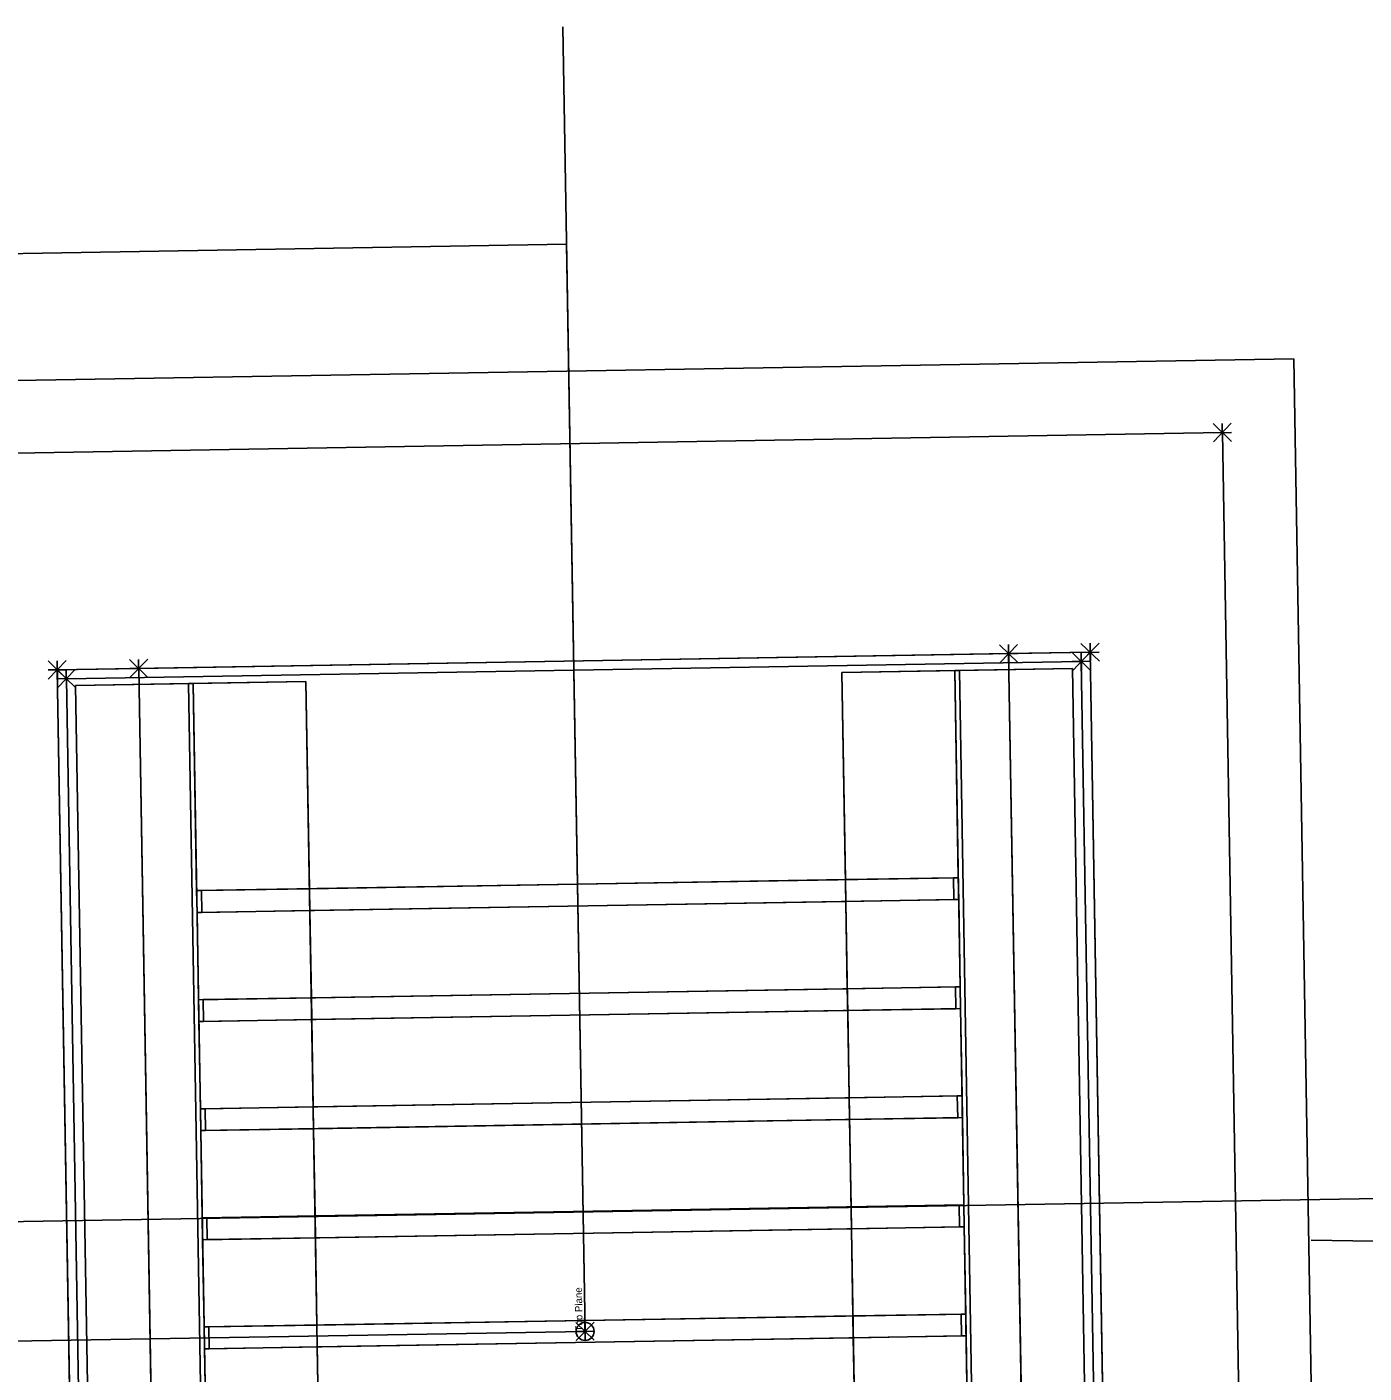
# Model space of a CAD drawing. Extents: x 925371 to 925937, y 853654 to 858024.
# Drawn here: x 925745.198 to 925748.272, y 853953.462 to 853956.558 of the extents above; entities that cross this region are included whole.
import ezdxf

# ---------------------------------------------------------------- set-up
doc = ezdxf.new("R2010")
doc.units = 0
for name, color, linetype in [('NonPlottingEle_dp', 7, 'Continuous'), ('PipeCulvert', 7, 'Continuous'), ('PipeCulvert_ex', 7, 'Continuous')]:
    doc.layers.add(name, color=color, linetype=linetype)

msp = doc.modelspace()

# ---------------------------------------------------------------- linework, layer by layer
at = {"layer": 'NonPlottingEle_dp'}
msp.add_lwpolyline([(925743.7004, 853937.7833), (925743.4284, 853953.781), (925751.9636, 853953.9261)], dxfattribs=at)
at = {"layer": 'PipeCulvert'}
msp.add_line((925748.1503, 853953.7676), (925856.5217, 853952.1731), dxfattribs=at)
at = {"layer": 'PipeCulvert_ex'}
for p, q in [((925746.4812, 853953.5581), (925746.4302, 853956.5577)), ((925744.7772, 853955.7378), (925748.1101, 853955.7945)), ((925748.1101, 853955.7945), (925744.7772, 853955.7378)), ((925748.1101, 853955.7945), (925748.1101, 853955.7945)), ((925748.1101, 853955.7945), (925748.1852, 853951.3784)), ((925748.1852, 853951.3784), (925748.1101, 853955.7945)), ((925747.6423, 853955.1198), (925745.2677, 853955.0794)), ((925745.4551, 853955.0826), (925747.4548, 853955.1166)), ((925747.4548, 853955.1166), (925747.6423, 853955.1198)), ((925747.4548, 853955.1166), (925747.4548, 853955.1166)), ((925747.5073, 853952.0337), (925747.4548, 853955.1166)), ((925747.5073, 853952.0337), (925747.4548, 853955.1166)), ((925747.6423, 853955.1198), (925747.6947, 853952.0369)), ((925747.6947, 853952.0369), (925747.6423, 853955.1198)), ((925747.6423, 853955.1198), (925747.6423, 853955.1198)), ((925745.2677, 853955.0794), (925745.4551, 853955.0826)), ((925745.4551, 853955.0826), (925745.4551, 853955.0826)), ((925745.4551, 853955.0826), (925745.5075, 853951.9997)), ((925745.4551, 853955.0826), (925745.5075, 853951.9997)), ((925747.3311, 853955.078), (925747.6013, 853955.0826)), ((925747.6013, 853955.0826), (925747.3419, 853955.0782)), ((925747.6525, 853952.0726), (925747.6013, 853955.0826)), ((925747.6525, 853952.0726), (925747.6013, 853955.0826)), ((925747.6013, 853955.0826), (925747.6013, 853955.0826)), ((925745.3201, 853951.9965), (925745.2677, 853955.0794)), ((925745.2677, 853955.0794), (925745.3201, 853951.9965)), ((925745.2677, 853955.0794), (925745.2677, 853955.0794)), ((925745.5693, 853955.048), (925745.8395, 853955.0526)), ((925745.8395, 853955.0526), (925745.5801, 853955.0482)), ((925745.8907, 853952.0427), (925745.8395, 853955.0526)), ((925745.8476, 853954.5761), (925745.8395, 853955.0526)), ((925745.8395, 853955.0526), (925745.8395, 853955.0526)), ((925747.3419, 853955.0782), (925747.0717, 853955.0736)), ((925747.0717, 853955.0736), (925747.3311, 853955.078)), ((925747.1229, 853952.0636), (925747.0717, 853955.0736)), ((925747.0798, 853954.597), (925747.0717, 853955.0736)), ((925747.0717, 853955.0736), (925747.0717, 853955.0736)), ((925747.3822, 853952.068), (925747.3311, 853955.078)), ((925747.3392, 853954.6014), (925747.3311, 853955.078)), ((925747.3311, 853955.078), (925747.3311, 853955.078)), ((925747.3931, 853952.0682), (925747.3419, 853955.0782)), ((925747.3931, 853952.0682), (925747.3419, 853955.0782)), ((925747.3419, 853955.0782), (925747.3419, 853955.0782)), ((925745.5801, 853955.0482), (925745.3099, 853955.0436)), ((925745.3099, 853955.0436), (925745.5693, 853955.048)), ((925745.3611, 853952.0337), (925745.3099, 853955.0436)), ((925745.3611, 853952.0337), (925745.3099, 853955.0436)), ((925745.3099, 853955.0436), (925745.3099, 853955.0436)), ((925745.6205, 853952.0381), (925745.5693, 853955.048)), ((925745.6205, 853952.0381), (925745.5693, 853955.048)), ((925745.5693, 853955.048), (925745.5693, 853955.048)), ((925745.6313, 853952.0382), (925745.5801, 853955.0482)), ((925745.5882, 853954.5716), (925745.5801, 853955.0482)), ((925745.5801, 853955.0482), (925745.5801, 853955.0482)), ((925747.3392, 853954.6014), (925745.5882, 853954.5716)), ((925745.8476, 853954.5761), (925747.0798, 853954.597)), ((925747.0798, 853954.597), (925747.3284, 853954.6012)), ((925747.0806, 853954.5468), (925747.0798, 853954.597)), ((925747.3284, 853954.6012), (925747.3392, 853954.6014)), ((925747.3292, 853954.5511), (925747.3284, 853954.6012)), ((925747.34, 853954.5513), (925747.3392, 853954.6014)), ((925747.3392, 853954.6014), (925747.3392, 853954.6014)), ((925745.5882, 853954.5716), (925745.5991, 853954.5718)), ((925745.5891, 853954.5215), (925745.5882, 853954.5716)), ((925745.5882, 853954.5716), (925745.5882, 853954.5716)), ((925745.5991, 853954.5718), (925745.8476, 853954.5761)), ((925745.5999, 853954.5217), (925745.5991, 853954.5718)), ((925745.8485, 853954.5259), (925745.8476, 853954.5761)), ((925747.34, 853954.5513), (925745.5891, 853954.5215)), ((925745.5999, 853954.5217), (925745.8485, 853954.5259)), ((925745.8485, 853954.5259), (925747.0806, 853954.5468)), ((925745.8519, 853954.3252), (925745.8485, 853954.5259)), ((925747.0806, 853954.5468), (925747.3292, 853954.5511)), ((925747.084, 853954.3462), (925747.0806, 853954.5468)), ((925747.3292, 853954.5511), (925747.34, 853954.5513)), ((925747.3434, 853954.3506), (925747.34, 853954.5513)), ((925747.34, 853954.5513), (925747.34, 853954.5513)), ((925745.5891, 853954.5215), (925745.5999, 853954.5217)), ((925745.5925, 853954.3208), (925745.5891, 853954.5215)), ((925745.5891, 853954.5215), (925745.5891, 853954.5215)), ((925747.3434, 853954.3506), (925745.5925, 853954.3208)), ((925745.8519, 853954.3252), (925747.084, 853954.3462)), ((925747.084, 853954.3462), (925747.3326, 853954.3504)), ((925747.0849, 853954.296), (925747.084, 853954.3462)), ((925747.3326, 853954.3504), (925747.3434, 853954.3506)), ((925747.3335, 853954.3002), (925747.3326, 853954.3504)), ((925747.3443, 853954.3004), (925747.3434, 853954.3506)), ((925747.3434, 853954.3506), (925747.3434, 853954.3506)), ((925745.5925, 853954.3208), (925745.6033, 853954.321)), ((925745.5934, 853954.2706), (925745.5925, 853954.3208)), ((925745.5925, 853954.3208), (925745.5925, 853954.3208)), ((925745.6033, 853954.321), (925745.8519, 853954.3252)), ((925745.6042, 853954.2708), (925745.6033, 853954.321)), ((925745.8528, 853954.2751), (925745.8519, 853954.3252)), ((925747.3443, 853954.3004), (925745.5934, 853954.2706)), ((925745.8528, 853954.2751), (925747.0849, 853954.296)), ((925747.0849, 853954.296), (925747.3335, 853954.3002)), ((925747.0883, 853954.0953), (925747.0849, 853954.296)), ((925747.3335, 853954.3002), (925747.3443, 853954.3004)), ((925747.3477, 853954.0998), (925747.3443, 853954.3004)), ((925747.3443, 853954.3004), (925747.3443, 853954.3004)), ((925745.5934, 853954.2706), (925745.6042, 853954.2708)), ((925745.5968, 853954.07), (925745.5934, 853954.2706)), ((925745.5934, 853954.2706), (925745.5934, 853954.2706)), ((925745.6042, 853954.2708), (925745.8528, 853954.2751)), ((925745.8562, 853954.0744), (925745.8528, 853954.2751)), ((925747.3477, 853954.0998), (925745.5968, 853954.07)), ((925745.8562, 853954.0744), (925747.0883, 853954.0953)), ((925747.0883, 853954.0953), (925747.3369, 853954.0996)), ((925747.0892, 853954.0452), (925747.0883, 853954.0953)), ((925747.3369, 853954.0996), (925747.3477, 853954.0998)), ((925747.3377, 853954.0494), (925747.3369, 853954.0996)), ((925747.3486, 853954.0496), (925747.3477, 853954.0998)), ((925747.3477, 853954.0998), (925747.3477, 853954.0998)), ((925745.5968, 853954.07), (925745.6076, 853954.0702)), ((925745.5976, 853954.0198), (925745.5968, 853954.07)), ((925745.5968, 853954.07), (925745.5968, 853954.07)), ((925745.6076, 853954.0702), (925745.8562, 853954.0744)), ((925745.6084, 853954.02), (925745.6076, 853954.0702)), ((925745.857, 853954.0242), (925745.8562, 853954.0744)), ((925747.3486, 853954.0496), (925745.5976, 853954.0198)), ((925745.857, 853954.0242), (925747.0892, 853954.0452)), ((925747.0892, 853954.0452), (925747.3377, 853954.0494)), ((925747.0926, 853953.8445), (925747.0892, 853954.0452)), ((925747.3377, 853954.0494), (925747.3486, 853954.0496)), ((925747.352, 853953.8489), (925747.3486, 853954.0496)), ((925747.3486, 853954.0496), (925747.3486, 853954.0496)), ((925745.5976, 853954.0198), (925745.6084, 853954.02)), ((925745.601, 853953.8192), (925745.5976, 853954.0198)), ((925745.5976, 853954.0198), (925745.5976, 853954.0198)), ((925745.6084, 853954.02), (925745.857, 853954.0242)), ((925745.8604, 853953.8236), (925745.857, 853954.0242)), ((925747.352, 853953.8489), (925745.601, 853953.8192)), ((925745.8604, 853953.8236), (925747.0926, 853953.8445)), ((925747.0926, 853953.8445), (925747.3412, 853953.8487)), ((925747.0934, 853953.7943), (925747.0926, 853953.8445)), ((925747.3412, 853953.8487), (925747.352, 853953.8489)), ((925747.342, 853953.7986), (925747.3412, 853953.8487)), ((925747.3528, 853953.7988), (925747.352, 853953.8489)), ((925747.352, 853953.8489), (925747.352, 853953.8489)), ((925745.601, 853953.8192), (925745.6118, 853953.8193)), ((925745.6019, 853953.769), (925745.601, 853953.8192)), ((925745.601, 853953.8192), (925745.601, 853953.8192)), ((925745.6118, 853953.8193), (925745.8604, 853953.8236)), ((925745.6127, 853953.7692), (925745.6118, 853953.8193)), ((925745.8613, 853953.7734), (925745.8604, 853953.8236)), ((925747.3528, 853953.7988), (925745.6019, 853953.769)), ((925745.8613, 853953.7734), (925747.0934, 853953.7943)), ((925747.0934, 853953.7943), (925747.342, 853953.7986)), ((925747.0968, 853953.5937), (925747.0934, 853953.7943)), ((925747.342, 853953.7986), (925747.3528, 853953.7988)), ((925747.3562, 853953.5981), (925747.3528, 853953.7988)), ((925747.3528, 853953.7988), (925747.3528, 853953.7988)), ((925745.6019, 853953.769), (925745.6127, 853953.7692)), ((925745.6053, 853953.5683), (925745.6019, 853953.769)), ((925745.6019, 853953.769), (925745.6019, 853953.769)), ((925745.6127, 853953.7692), (925745.8613, 853953.7734)), ((925745.8647, 853953.5727), (925745.8613, 853953.7734)), ((925747.3562, 853953.5981), (925745.6053, 853953.5683)), ((925747.0968, 853953.5937), (925747.3454, 853953.5979)), ((925747.3454, 853953.5979), (925747.3562, 853953.5981)), ((925747.3463, 853953.5477), (925747.3454, 853953.5979)), ((925747.3571, 853953.5479), (925747.3562, 853953.5981)), ((925747.3562, 853953.5981), (925747.3562, 853953.5981)), ((925745.6053, 853953.5683), (925745.6161, 853953.5685)), ((925745.6062, 853953.5182), (925745.6053, 853953.5683)), ((925745.6053, 853953.5683), (925745.6053, 853953.5683)), ((925745.6161, 853953.5685), (925745.8647, 853953.5727)), ((925745.617, 853953.5183), (925745.6161, 853953.5685)), ((925745.8647, 853953.5727), (925747.0968, 853953.5937)), ((925745.8656, 853953.5226), (925745.8647, 853953.5727)), ((925747.0977, 853953.5435), (925747.0968, 853953.5937)), ((925747.3571, 853953.5479), (925745.6062, 853953.5182)), ((925745.8656, 853953.5226), (925747.0977, 853953.5435)), ((925746.4812, 853953.5581), (925746.4812, 853953.5581)), ((925746.4812, 853953.5581), (925746.4812, 853953.5581)), ((925747.0977, 853953.5435), (925747.3463, 853953.5477)), ((925747.1011, 853953.3428), (925747.0977, 853953.5435)), ((925747.3463, 853953.5477), (925747.3571, 853953.5479)), ((925747.3605, 853953.3473), (925747.3571, 853953.5479)), ((925747.3571, 853953.5479), (925747.3571, 853953.5479)), ((925745.6062, 853953.5182), (925745.617, 853953.5183)), ((925745.6096, 853953.3175), (925745.6062, 853953.5182)), ((925745.6062, 853953.5182), (925745.6062, 853953.5182)), ((925745.617, 853953.5183), (925745.8656, 853953.5226)), ((925745.869, 853953.3219), (925745.8656, 853953.5226))]:
    msp.add_line(p, q, dxfattribs=at)
for points in [[(925746.4387, 853956.0578), (925743.9391, 853956.0153)], [(925746.4812, 853953.5581), (925746.4387, 853956.0578)], [(925747.9674, 853955.6045), (925747.9251, 853955.6455)], [(925747.9258, 853955.6038), (925747.9667, 853955.6462)], [(925747.9466, 853955.6042), (925747.9459, 853955.6458)], [(925747.9463, 853955.625), (925744.9467, 853955.574)], [(925747.9463, 853955.625), (925744.9467, 853955.574)], [(925747.9463, 853955.625), (925744.9467, 853955.574)], [(925747.9463, 853955.625), (925744.9467, 853955.574)], [(925747.9463, 853955.625), (925744.9467, 853955.574)], [(925747.9671, 853955.6253), (925747.9254, 853955.6246)], [(925747.9463, 853955.625), (925747.9463, 853955.625)], [(925748.0157, 853951.5423), (925747.9463, 853955.625)], [(925748.0157, 853951.5423), (925747.9463, 853955.625)], [(925747.9463, 853955.625), (925747.9463, 853955.625)], [(925747.9463, 853955.625), (925747.9463, 853955.625)], [(925748.0157, 853951.5423), (925747.9463, 853955.625)], [(925747.9463, 853955.625), (925747.9463, 853955.625)], [(925748.0157, 853951.5423), (925747.9463, 853955.625)], [(925748.0157, 853951.5423), (925747.9463, 853955.625)], [(925747.9463, 853955.625), (925747.9463, 853955.625)], [(925747.9463, 853955.625), (925747.9463, 853955.625)], [(925747.6423, 853955.1197), (925745.2677, 853955.0794)], [(925747.6423, 853955.1197), (925745.2677, 853955.0794)], [(925747.6423, 853955.1197), (925745.2677, 853955.0794)], [(925747.4548, 853955.1166), (925745.4551, 853955.0826)], [(925747.4548, 853955.1166), (925745.4551, 853955.0826)], [(925747.4548, 853955.1166), (925745.4551, 853955.0826)], [(925747.4548, 853955.1166), (925745.4551, 853955.0826)], [(925745.4551, 853955.0826), (925747.4548, 853955.1166)], [(925747.476, 853955.0961), (925747.4337, 853955.137)], [(925747.4757, 853955.1169), (925747.434, 853955.1162)], [(925747.4344, 853955.0954), (925747.4753, 853955.1377)], [(925747.4552, 853955.0957), (925747.4545, 853955.1374)], [(925747.4548, 853955.1166), (925747.4548, 853955.1166)], [(925747.5073, 853952.0337), (925747.4548, 853955.1166)], [(925747.5073, 853952.0337), (925747.4548, 853955.1166)], [(925747.4548, 853955.1166), (925747.4548, 853955.1166)], [(925747.4548, 853955.1166), (925747.4548, 853955.1166)], [(925747.5073, 853952.0337), (925747.4548, 853955.1166)], [(925747.4548, 853955.1166), (925747.4548, 853955.1166)], [(925747.5073, 853952.0337), (925747.4548, 853955.1166)], [(925747.4548, 853955.1166), (925747.5073, 853952.0337)], [(925747.4548, 853955.1166), (925747.4548, 853955.1166)], [(925747.4548, 853955.1166), (925747.4548, 853955.1166)], [(925747.643, 853955.0781), (925747.6007, 853955.119)], [(925747.6014, 853955.0774), (925747.6423, 853955.1197)], [(925747.6635, 853955.0993), (925747.6211, 853955.1402)], [(925747.6631, 853955.1201), (925747.6215, 853955.1194)], [(925747.6222, 853955.0777), (925747.6215, 853955.1194)], [(925747.6218, 853955.0986), (925747.6628, 853955.1409)], [(925747.6427, 853955.0989), (925747.642, 853955.1406)], [(925747.6423, 853955.1197), (925747.6423, 853955.1197)], [(925747.6947, 853952.0369), (925747.6423, 853955.1197)], [(925747.6947, 853952.0369), (925747.6423, 853955.1197)], [(925747.6423, 853955.1197), (925747.6423, 853955.1197)], [(925747.6423, 853955.1197), (925747.6423, 853955.1197)], [(925747.6947, 853952.0369), (925747.6423, 853955.1197)], [(925745.2888, 853955.0589), (925745.2465, 853955.0998)], [(925745.2472, 853955.0582), (925745.2881, 853955.1006)], [(925745.268, 853955.0585), (925745.2673, 853955.1002)], [(925747.6218, 853955.0986), (925745.2888, 853955.0589)], [(925745.4763, 853955.0621), (925745.4339, 853955.103)], [(925745.476, 853955.0829), (925745.4343, 853955.0822)], [(925745.4347, 853955.0614), (925745.4756, 853955.1037)], [(925745.4555, 853955.0617), (925745.4548, 853955.1034)], [(925745.4551, 853955.0826), (925745.5075, 853951.9997)], [(925745.4551, 853955.0826), (925745.4551, 853955.0826)], [(925745.4551, 853955.0826), (925745.5075, 853951.9997)], [(925745.4551, 853955.0826), (925745.4551, 853955.0826)], [(925745.4551, 853955.0826), (925745.4551, 853955.0826)], [(925745.4551, 853955.0826), (925745.5075, 853951.9997)], [(925745.4551, 853955.0826), (925745.5075, 853951.9997)], [(925745.4551, 853955.0826), (925745.4551, 853955.0826)], [(925745.5075, 853951.9997), (925745.4551, 853955.0826)], [(925745.4551, 853955.0826), (925745.4551, 853955.0826)], [(925745.4551, 853955.0826), (925745.4551, 853955.0826)], [(925747.6427, 853955.0989), (925747.601, 853955.0982)], [(925747.6735, 853952.0573), (925747.6218, 853955.0986)], [(925745.2885, 853955.0797), (925745.2468, 853955.079)], [(925745.2677, 853955.0794), (925745.3201, 853951.9965)], [(925745.2677, 853955.0794), (925745.2677, 853955.0794)], [(925745.2677, 853955.0794), (925745.3201, 853951.9965)], [(925745.2677, 853955.0794), (925745.2677, 853955.0794)], [(925745.2677, 853955.0794), (925745.2677, 853955.0794)], [(925745.2677, 853955.0794), (925745.3201, 853951.9965)], [(925745.31, 853955.0384), (925745.2677, 853955.0794)], [(925745.3097, 853955.0593), (925745.268, 853955.0585)], [(925745.2684, 853955.0377), (925745.3093, 853955.0801)], [(925745.2892, 853955.0381), (925745.2885, 853955.0797)], [(925745.2888, 853955.0589), (925745.3406, 853952.0177)], [(925746.5024, 853953.5376), (925746.46, 853953.5786)], [(925746.4607, 853953.5369), (925746.5017, 853953.5793)], [(925746.4815, 853953.5373), (925746.4808, 853953.579)], [(925743.9816, 853953.5156), (925746.4812, 853953.5581)], [(925746.502, 853953.5585), (925746.4604, 853953.5578)]]:
    msp.add_lwpolyline(points, dxfattribs=at)
msp.add_circle((925746.4812, 853953.5581), 0.0208, dxfattribs=at)

# ---------------------------------------------------------------- texts
msp.add_text('Top Plane', height=0.01667, rotation=90.9741, dxfattribs=at).set_placement((925746.4756, 853953.558))

doc.saveas('drawing.dxf')
